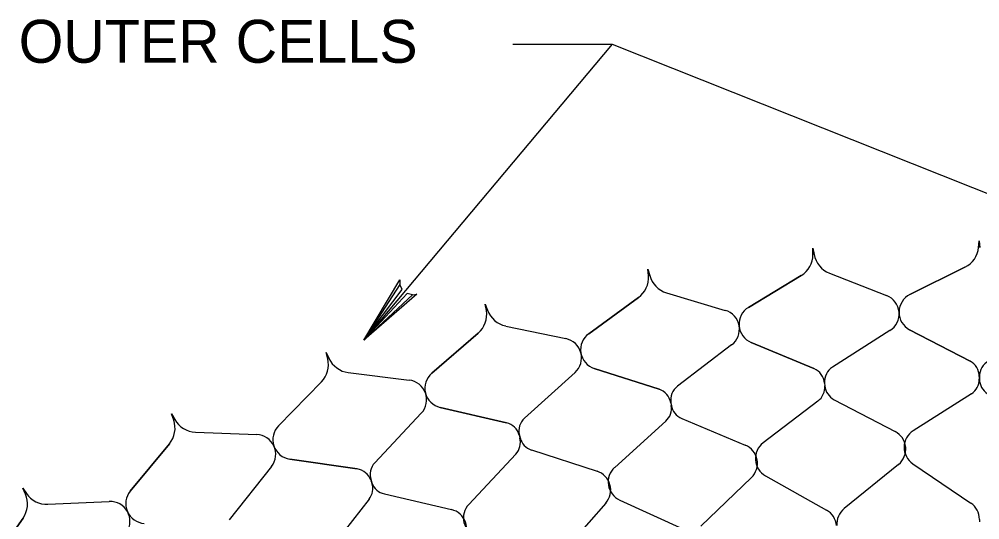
# Model space of a CAD drawing. Extents: x 638850 to 644908, y 297188 to 298900.
# Drawn here: x 639777.9 to 639845, y 297670.4 to 297705.4 of the extents above; entities that cross this region are included whole.
import ezdxf

# ---------------------------------------------------------------- set-up
doc = ezdxf.new("R2010")
doc.units = 0
for name, color, linetype in [('1', 7, 'Continuous'), ('5', 7, 'Continuous'), ('50', 7, 'Continuous'), ('9', 7, 'Continuous')]:
    doc.layers.add(name, color=color, linetype=linetype)

msp = doc.modelspace()

# ---------------------------------------------------------------- linework, layer by layer
at = {"layer": '1'}
for q in [(639801.934, 297682.963), (639849.803, 297691.499)]:
    msp.add_line((639819.279, 297703.63), q, dxfattribs=at)
msp.add_lwpolyline([(639805.343, 297686.124), (639804.977, 297686.207), (639801.934, 297682.963), (639805.343, 297686.124), (639805.65, 297686.175), (639801.934, 297682.963), (639804.618, 297686.503), (639804.47, 297686.84), (639801.934, 297682.963), (639804.461, 297687.173), (639804.47, 297686.84)], dxfattribs=at)
at = {"layer": '5'}
for p, q in [((639833.317, 297689.391), (639833.314, 297688.934)), ((639833.317, 297689.391), (639833.398, 297688.941)), ((639844.926, 297689.896), (639844.885, 297689.441)), ((639844.926, 297689.896), (639844.968, 297689.441)), ((639843.935, 297688.052), (639840.092, 297686.143)), ((639821.792, 297687.915), (639821.827, 297687.459)), ((639821.792, 297687.915), (639821.91, 297687.474)), ((639832.485, 297687.471), (639828.815, 297685.246)), ((639834.464, 297687.64), (639838.459, 297686.072)), ((639823.081, 297686.267), (639827.193, 297685.038)), ((639810.431, 297685.48), (639810.504, 297685.029)), ((639810.431, 297685.48), (639810.585, 297685.049)), ((639821.123, 297685.932), (639817.653, 297683.408)), ((639809.93, 297683.448), (639806.683, 297680.642)), ((639811.854, 297683.945), (639816.054, 297683.065)), ((639838.694, 297683.625), (639834.685, 297681.076)), ((639840.07, 297683.685), (639844.285, 297681.494)), ((639828.998, 297682.795), (639833.383, 297680.964)), ((639799.313, 297682.101), (639799.424, 297681.658)), ((639799.313, 297682.101), (639799.503, 297681.686)), ((639827.633, 297682.62), (639823.851, 297679.744)), ((639800.86, 297680.691), (639805.119, 297680.166)), ((639816.695, 297680.692), (639813.167, 297677.51)), ((639818.041, 297680.981), (639822.563, 297679.524)), ((639798.985, 297680.034), (639795.984, 297676.966)), ((639844.935, 297680.424), (639844.935, 297680.232)), ((639844.946, 297680.424), (639844.946, 297680.232)), ((639834.12, 297679.953), (639834.136, 297679.761)), ((639834.131, 297679.954), (639834.147, 297679.762)), ((639833.666, 297678.7), (639829.839, 297675.779)), ((639834.791, 297678.796), (639839.059, 297676.569)), ((639844.378, 297679.214), (639840.319, 297676.624)), ((639807.273, 297678.256), (639811.902, 297677.182)), ((639823.382, 297678.578), (639823.414, 297678.388)), ((639823.393, 297678.58), (639823.425, 297678.39)), ((639788.518, 297677.804), (639788.666, 297677.371)), ((639788.518, 297677.804), (639788.742, 297677.405)), ((639805.956, 297677.855), (639802.708, 297674.388)), ((639823.035, 297677.291), (639819.465, 297674.06)), ((639824.148, 297677.482), (639828.588, 297675.619)), ((639790.177, 297676.528), (639794.465, 297676.362)), ((639812.797, 297676.308), (639812.845, 297676.122)), ((639812.808, 297676.311), (639812.856, 297676.125)), ((639788.364, 297675.717), (639785.631, 297672.408)), ((639813.652, 297675.28), (639818.232, 297673.796)), ((639796.772, 297674.638), (639801.474, 297673.956)), ((639812.559, 297674.997), (639809.272, 297671.479)), ((639795.493, 297674.129), (639792.546, 297670.402)), ((639839.292, 297674.278), (639835.495, 297671.187)), ((639840.287, 297674.321), (639844.338, 297671.572)), ((639829.011, 297673.355), (639825.486, 297669.958)), ((639829.999, 297673.482), (639834.266, 297671.082)), ((639778.12, 297672.617), (639778.304, 297672.199)), ((639778.12, 297672.617), (639778.377, 297672.239)), ((639802.439, 297673.16), (639802.503, 297672.978)), ((639802.45, 297673.164), (639802.514, 297672.982)), ((639803.377, 297672.207), (639808.066, 297671.112)), ((639779.88, 297671.485), (639784.168, 297671.678)), ((639802.312, 297671.834), (639799.332, 297668.052)), ((639818.844, 297671.576), (639815.616, 297667.895)), ((639819.818, 297671.784), (639824.271, 297669.75)), ((639778.141, 297670.525), (639775.695, 297666.999)), ((639844.943, 297670.432), (639844.943, 297670.259))]:
    msp.add_line(p, q, dxfattribs=at)
for centre, radius, start, end in [((639843.168, 297689.596), 1.723, 296.42312, 354.84557), ((639831.591, 297688.944), 1.723, 301.22669, 359.64914), ((639835.094, 297689.244), 1.723, 190.13895, 248.5614), ((639820.109, 297687.326), 1.723, 306.03027, 4.45271), ((639823.575, 297687.918), 1.723, 194.94252, 253.36497), ((639837.955, 297684.788), 1.379, 302.45157, 68.5614), ((639840.705, 297684.908), 1.379, 116.42312, 242.53295), ((639808.804, 297684.751), 1.723, 310.83384, 9.25628), ((639812.207, 297685.632), 1.723, 199.74609, 258.16854), ((639826.799, 297683.717), 1.379, 307.25514, 73.36497), ((639829.53, 297684.067), 1.379, 121.22669, 247.33652), ((639818.463, 297682.293), 1.379, 126.03027, 252.14009), ((639815.771, 297681.716), 1.379, 312.05871, 78.16854), ((639797.753, 297681.239), 1.723, 315.63741, 14.05985), ((639801.071, 297682.401), 1.723, 204.54966, 262.97211), ((639843.729, 297680.423), 1.206, 0.04729, 62.53295), ((639846.152, 297680.427), 1.206, 117.648, 180.13365), ((639832.918, 297679.851), 1.206, 4.85087, 67.33652), ((639835.332, 297680.058), 1.206, 122.45157, 184.93722), ((639804.95, 297678.798), 1.379, 316.86228, 82.97211), ((639807.585, 297679.599), 1.379, 130.83384, 256.94366), ((639843.729, 297680.231), 1.206, 302.5441, 0.0473), ((639846.153, 297680.234), 1.206, 180.13365, 237.63685), ((639822.193, 297678.376), 1.206, 9.65444, 72.14009), ((639824.582, 297678.784), 1.206, 127.25514, 189.7408), ((639832.934, 297679.659), 1.206, 307.34767, 4.85087), ((639835.349, 297679.866), 1.206, 184.93722, 242.44042), ((639822.225, 297678.186), 1.206, 312.15124, 9.65444), ((639824.614, 297678.594), 1.206, 189.74079, 247.24399), ((639787.035, 297676.814), 1.723, 320.44098, 18.86342), ((639790.244, 297678.25), 1.723, 209.35323, 267.77568), ((639813.975, 297676.614), 1.206, 132.05871, 194.54437), ((639796.97, 297676.003), 1.379, 135.63741, 261.74723), ((639811.629, 297676.007), 1.206, 14.45801, 76.94366), ((639841.061, 297675.462), 1.379, 122.5441, 235.84026), ((639794.412, 297674.984), 1.379, 321.66585, 87.77568), ((639811.677, 297675.821), 1.206, 316.95481, 14.45801), ((639814.024, 297676.427), 1.206, 194.54436, 252.04756), ((639838.422, 297675.347), 1.379, 309.14426, 62.44042), ((639828.054, 297674.348), 1.379, 313.94783, 67.24399), ((639830.675, 297674.683), 1.379, 127.34767, 240.64383), ((639801.301, 297672.763), 1.206, 19.26158, 81.74723), ((639803.588, 297673.564), 1.206, 136.86228, 199.34794), ((639820.39, 297673.038), 1.379, 132.15124, 245.4474), ((639817.807, 297672.485), 1.379, 318.7514, 72.04756), ((639801.364, 297672.58), 1.206, 321.75838, 19.26158), ((639803.652, 297673.382), 1.206, 199.34793, 256.85113), ((639776.726, 297671.507), 1.723, 325.24455, 23.66699), ((639779.803, 297673.207), 1.723, 214.1568, 272.57925), ((639786.693, 297671.53), 1.379, 140.44098, 266.5508), ((639784.23, 297670.301), 1.379, 326.46942, 92.57925), ((639810.28, 297670.538), 1.379, 136.95481, 250.25097), ((639843.564, 297670.431), 1.379, 0.04735, 55.84026), ((639807.752, 297669.77), 1.379, 323.55497, 76.85113), ((639833.59, 297669.88), 1.379, 4.85092, 60.64383), ((639836.365, 297670.118), 1.379, 129.14426, 184.93717)]:
    msp.add_arc(centre, radius, start, end, dxfattribs=at)
at = {"layer": '50'}
for p, q in [((639833.314, 297688.934), (639833.317, 297689.391)), ((639833.317, 297689.391), (639833.398, 297688.941)), ((639844.885, 297689.441), (639844.926, 297689.896)), ((639844.926, 297689.896), (639844.968, 297689.441)), ((639840.092, 297686.143), (639843.935, 297688.052)), ((639821.827, 297687.459), (639821.792, 297687.915)), ((639821.792, 297687.915), (639821.91, 297687.474)), ((639828.815, 297685.246), (639832.485, 297687.471)), ((639834.464, 297687.64), (639838.459, 297686.072)), ((639823.081, 297686.267), (639827.193, 297685.038)), ((639810.504, 297685.029), (639810.431, 297685.48)), ((639810.431, 297685.48), (639810.585, 297685.049)), ((639817.653, 297683.408), (639821.123, 297685.932)), ((639806.683, 297680.642), (639809.93, 297683.448)), ((639811.854, 297683.945), (639816.054, 297683.065)), ((639838.694, 297683.625), (639834.685, 297681.076)), ((639844.285, 297681.494), (639840.07, 297683.685)), ((639833.383, 297680.964), (639828.998, 297682.795)), ((639799.424, 297681.658), (639799.313, 297682.101)), ((639799.313, 297682.101), (639799.503, 297681.686)), ((639827.633, 297682.62), (639823.851, 297679.744)), ((639800.86, 297680.691), (639805.119, 297680.166)), ((639816.695, 297680.692), (639813.167, 297677.51)), ((639822.563, 297679.524), (639818.041, 297680.981)), ((639795.984, 297676.966), (639798.985, 297680.034)), ((639811.902, 297677.182), (639807.273, 297678.256)), ((639788.666, 297677.371), (639788.518, 297677.804)), ((639788.518, 297677.804), (639788.742, 297677.405)), ((639805.956, 297677.855), (639802.708, 297674.388)), ((639790.177, 297676.528), (639794.465, 297676.362)), ((639785.631, 297672.408), (639788.364, 297675.717)), ((639801.474, 297673.956), (639796.772, 297674.638)), ((639795.493, 297674.129), (639792.546, 297670.402)), ((639778.304, 297672.199), (639778.12, 297672.617)), ((639778.12, 297672.617), (639778.377, 297672.239)), ((639779.88, 297671.485), (639784.168, 297671.678)), ((639775.695, 297666.999), (639778.141, 297670.525))]:
    msp.add_line(p, q, dxfattribs=at)
for centre, radius, start, end in [((639843.168, 297689.596), 1.723, 296.42313, 354.84557), ((639831.591, 297688.944), 1.723, 301.2267, 359.64914), ((639835.094, 297689.244), 1.723, 190.13895, 248.5614), ((639820.109, 297687.326), 1.723, 306.03026, 4.45271), ((639823.575, 297687.918), 1.723, 194.94252, 253.36497), ((639837.955, 297684.788), 1.379, 302.45157, 68.5614), ((639840.705, 297684.908), 1.379, 116.42313, 242.53295), ((639808.804, 297684.751), 1.723, 310.83384, 9.25628), ((639812.207, 297685.632), 1.723, 199.74609, 258.16854), ((639826.799, 297683.717), 1.379, 307.25514, 73.36497), ((639829.53, 297684.067), 1.379, 121.22669, 247.33652), ((639818.463, 297682.293), 1.379, 126.03026, 252.14009), ((639815.771, 297681.716), 1.379, 312.05871, 78.16854), ((639797.753, 297681.239), 1.723, 315.63741, 14.05985), ((639801.071, 297682.401), 1.723, 204.54966, 262.97211), ((639843.729, 297680.423), 1.206, 0.04729, 62.53295), ((639846.152, 297680.427), 1.206, 117.648, 180.13365), ((639832.918, 297679.851), 1.206, 4.85086, 67.33651), ((639835.332, 297680.058), 1.206, 122.45157, 184.93722), ((639804.95, 297678.798), 1.379, 316.86228, 82.97211), ((639807.585, 297679.599), 1.379, 130.83384, 256.94366), ((639822.193, 297678.376), 1.206, 9.65444, 72.14009), ((639824.582, 297678.784), 1.206, 127.25514, 189.7408), ((639787.035, 297676.814), 1.723, 320.44097, 18.86342), ((639790.244, 297678.25), 1.723, 209.35323, 267.77568), ((639813.975, 297676.614), 1.206, 132.05871, 194.54437), ((639796.97, 297676.003), 1.379, 135.63741, 261.74723), ((639811.629, 297676.007), 1.206, 14.45801, 76.94366), ((639794.412, 297674.984), 1.379, 321.66585, 87.77568), ((639801.301, 297672.763), 1.206, 19.26157, 81.74723), ((639803.588, 297673.564), 1.206, 136.86228, 199.34794), ((639776.726, 297671.507), 1.723, 325.24454, 23.66699), ((639779.803, 297673.207), 1.723, 214.1568, 272.57925), ((639786.693, 297671.53), 1.379, 140.44097, 266.5508), ((639784.23, 297670.301), 1.379, 326.46942, 92.57925)]:
    msp.add_arc(centre, radius, start, end, dxfattribs=at)
at = {"layer": '9'}
msp.add_line((639812.343, 297703.63), (639819.279, 297703.63), dxfattribs=at)

# ---------------------------------------------------------------- texts
at = {"layer": '1'}
msp.add_text('OUTER CELLS', height=3, dxfattribs=at).set_placement((639777.836, 297702.341))

doc.saveas('drawing.dxf')
